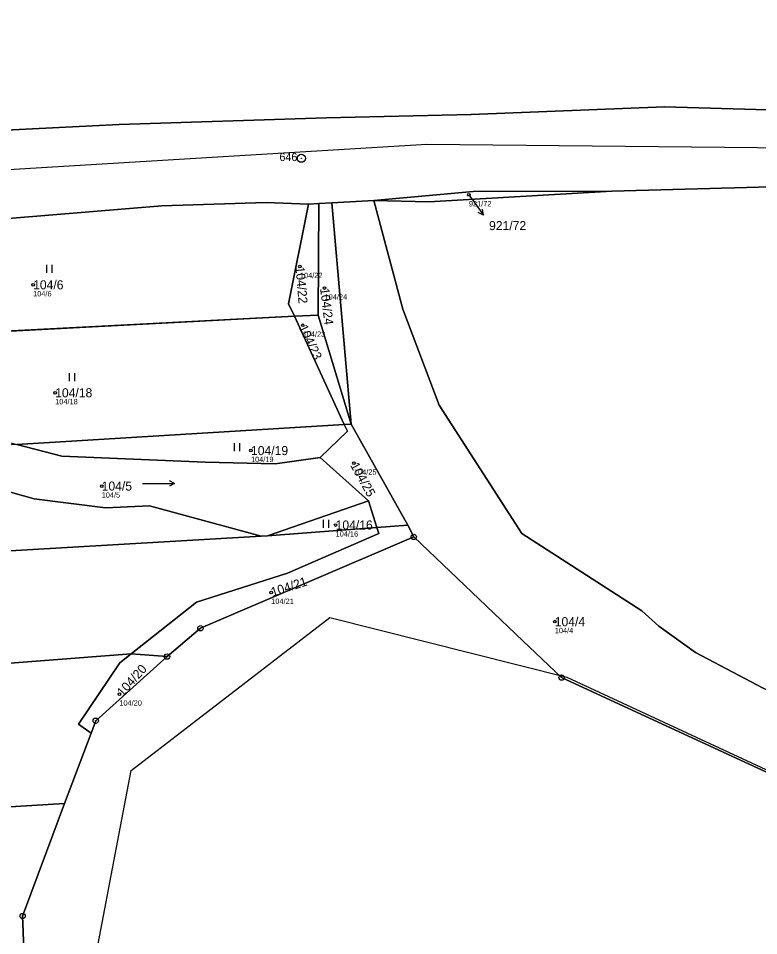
# Model space of a CAD drawing. Extents: x -734504 to -730695, y -1027923 to -1024502.
# Drawn here: x -731527.8 to -731389.2, y -1026155.5 to -1025983.6 of the extents above; entities that cross this region are included whole.
import ezdxf

# ---------------------------------------------------------------- set-up
doc = ezdxf.new("R2010")
doc.units = 0
for name, color, linetype in [('Definiční body', 7, 'Continuous'), ('Hranice parcel', 7, 'Continuous'), ('Parcelní čísla', 7, 'Continuous'), ('Polygon parcely', 7, 'Continuous'), ('Pop  PČ popisy', 7, 'Continuous'), ('Vnitřní kresba', 7, 'Continuous'), ('Značky bodu BP', 7, 'Continuous'), ('Značky kultur', 7, 'Continuous')]:
    doc.layers.add(name, color=color, linetype=linetype)

msp = doc.modelspace()

# ---------------------------------------------------------------- linework, layer by layer
at = {"layer": 'Definiční body'}
for centre in [(-731443.43, -1026016.73), (-731475.07, -1026030.16), (-731525.05, -1026033.58), (-731470.46, -1026034.18), (-731474.56, -1026041.16), (-731520.92, -1026053.81), (-731484.24, -1026064.64), (-731464.95, -1026067.01), (-731512.21, -1026071.29), (-731468.39, -1026078.59), (-731480.45, -1026091.22), (-731427.34, -1026096.7), (-731508.9, -1026110.27)]:
    msp.add_circle(centre, 0.25, dxfattribs=at)
at = {"layer": 'Hranice parcel'}
for p, q in [((-731477.2, -1026037.15), (-731473.47, -1026018.47)), ((-731473.47, -1026018.47), (-731471.55, -1026018.36)), ((-731471.68, -1026039.27), (-731471.55, -1026018.36)), ((-731471.55, -1026018.36), (-731469.07, -1026018.22)), ((-731461.25, -1026017.78), (-731469.07, -1026018.22)), ((-731469.07, -1026018.22), (-731465.5, -1026059.69)), ((-731476.12, -1026039.48), (-731477.2, -1026037.15)), ((-731568.83, -1026044.29), (-731476.12, -1026039.48)), ((-731476.12, -1026039.48), (-731471.68, -1026039.27)), ((-731466.76, -1026059.77), (-731476.12, -1026039.48)), ((-731465.5, -1026059.69), (-731471.68, -1026039.27)), ((-731528.11, -1026063.51), (-731466.76, -1026059.77)), ((-731466.76, -1026059.77), (-731465.5, -1026059.69)), ((-731466.19, -1026061.01), (-731466.76, -1026059.77)), ((-731465.5, -1026059.69), (-731454.89, -1026078.65)), ((-731471.3, -1026065.92), (-731466.19, -1026061.01)), ((-731462.23, -1026074.08), (-731471.3, -1026065.92)), ((-731481.14, -1026080.63), (-731462.23, -1026074.08)), ((-731460.65, -1026079.08), (-731462.23, -1026074.08)), ((-731460.65, -1026079.08), (-731481.14, -1026080.63)), ((-731454.89, -1026078.65), (-731460.65, -1026079.08)), ((-731454.89, -1026078.65), (-731453.76, -1026080.82)), ((-731580.71, -1026086.42), (-731482.31, -1026080.69)), ((-731482.31, -1026080.69), (-731481.14, -1026080.63)), ((-731506.7, -1026102.73), (-731588.4, -1026109.07)), ((-731499.97, -1026103.24), (-731506.7, -1026102.73)), ((-731514.2, -1026117.57), (-731519.15, -1026130.8)), ((-731519.15, -1026130.8), (-731596.66, -1026135.55))]:
    msp.add_line(p, q, dxfattribs=at)
for points in [[(-731897.94, -1025983.64), (-731862.07, -1025991.44), (-731847.22, -1025994.8), (-731827.82, -1025997.98), (-731799.13, -1026001.29), (-731775.22, -1026003.63), (-731763.84, -1026004.82), (-731742.5, -1026007.73), (-731730.75, -1026008.23), (-731698.59, -1026008.86), (-731662.59, -1026008.85), (-731619.31, -1026008.12), (-731589.11, -1026007.48), (-731575.19, -1026006.86), (-731508.93, -1026003.54), (-731470.15, -1026002.29), (-731442.98, -1026001.65), (-731406.79, -1026000.22), (-731383.28, -1026000.92)], [(-731311.13, -1026010.76), (-731350.25, -1026014.24), (-731416.63, -1026016)], [(-731416.63, -1026016), (-731450.95, -1026018.04), (-731461.25, -1026017.78)], [(-731461.25, -1026017.78), (-731449.48, -1026016.71), (-731442.63, -1026016.08), (-731416.63, -1026016)], [(-731473.47, -1026018.47), (-731481.39, -1026018.12), (-731500.93, -1026018.8), (-731528.93, -1026021.11), (-731573.67, -1026023.16)], [(-731461.25, -1026017.78), (-731455.79, -1026038.16), (-731448.97, -1026056.1), (-731433.52, -1026080.21), (-731411.05, -1026094.68), (-731407.88, -1026097.54), (-731400.99, -1026102.51), (-731376.79, -1026115.24), (-731363.17, -1026123.76), (-731346, -1026134.13), (-731334.78, -1026136.72)], [(-731471.3, -1026065.92), (-731479.74, -1026067.1), (-731492.82, -1026066.79), (-731519.69, -1026065.71), (-731528.11, -1026063.51)], [(-731555.24, -1026065.22), (-731541.77, -1026068.92), (-731524.83, -1026073.68), (-731511.48, -1026075.37), (-731503.25, -1026074.97), (-731482.31, -1026080.69)], [(-731506.7, -1026102.73), (-731494.43, -1026093.08), (-731477.42, -1026087.59), (-731460.31, -1026080.16), (-731460.65, -1026079.08)], [(-731453.76, -1026080.82), (-731493.71, -1026097.95), (-731499.97, -1026103.24)], [(-731453.76, -1026080.82), (-731433.31, -1026100.27), (-731426.05, -1026107.18), (-731411.21, -1026114.02), (-731343.39, -1026145.32)], [(-731514.2, -1026117.57), (-731516.54, -1026115.92), (-731508.81, -1026104.39), (-731506.7, -1026102.73)], [(-731499.97, -1026103.24), (-731513.33, -1026115.27), (-731514.2, -1026117.57)], [(-731519.15, -1026130.8), (-731522.52, -1026139.82), (-731527.02, -1026151.87), (-731526.93, -1026154.74), (-731526.81, -1026158.57)]]:
    msp.add_lwpolyline(points, dxfattribs=at)
at = {"layer": 'Polygon parcely'}
for points in [[(-731383.28, -1026000.92), (-731406.79, -1026000.22), (-731442.98, -1026001.65), (-731470.15, -1026002.29), (-731508.93, -1026003.54), (-731575.19, -1026006.86), (-731589.11, -1026007.48), (-731619.31, -1026008.12), (-731662.59, -1026008.85), (-731698.59, -1026008.86), (-731730.75, -1026008.23), (-731742.5, -1026007.73), (-731763.84, -1026004.82), (-731775.22, -1026003.63), (-731799.13, -1026001.29), (-731827.82, -1025997.98), (-731847.22, -1025994.8), (-731862.07, -1025991.44), (-731897.94, -1025983.64)], [(-731897.94, -1025983.64), (-731862.07, -1025991.44), (-731847.22, -1025994.8), (-731827.82, -1025997.98), (-731799.13, -1026001.29), (-731775.22, -1026003.63), (-731763.84, -1026004.82), (-731742.5, -1026007.73), (-731730.75, -1026008.23), (-731698.59, -1026008.86), (-731662.59, -1026008.85), (-731619.31, -1026008.12), (-731589.11, -1026007.48), (-731575.19, -1026006.86), (-731508.93, -1026003.54), (-731470.15, -1026002.29), (-731442.98, -1026001.65), (-731406.79, -1026000.22), (-731383.28, -1026000.92)], [(-731727.03, -1026023.83), (-731716.21, -1026023.81), (-731698.55, -1026023.77), (-731659.65, -1026023.51), (-731619.6, -1026023.97), (-731594.13, -1026022.85), (-731575.33, -1026023.13), (-731573.67, -1026023.16), (-731528.93, -1026021.11), (-731500.93, -1026018.8), (-731481.39, -1026018.12), (-731473.47, -1026018.47), (-731471.55, -1026018.36), (-731469.07, -1026018.22), (-731461.25, -1026017.78), (-731449.48, -1026016.71), (-731442.63, -1026016.08), (-731416.63, -1026016), (-731350.25, -1026014.24)], [(-731350.25, -1026014.24), (-731416.63, -1026016), (-731450.95, -1026018.04), (-731461.25, -1026017.78), (-731455.79, -1026038.16), (-731448.97, -1026056.1), (-731433.52, -1026080.21), (-731411.05, -1026094.68), (-731407.88, -1026097.54), (-731400.99, -1026102.51), (-731376.79, -1026115.24)], [(-731343.39, -1026145.32), (-731411.21, -1026114.02), (-731426.05, -1026107.18), (-731433.31, -1026100.27), (-731453.76, -1026080.82), (-731493.71, -1026097.95), (-731499.97, -1026103.24), (-731513.33, -1026115.27), (-731514.2, -1026117.57), (-731519.15, -1026130.8), (-731522.52, -1026139.82), (-731527.02, -1026151.87), (-731526.93, -1026154.74), (-731526.81, -1026158.57)]]:
    msp.add_lwpolyline(points, dxfattribs=at)
for points in [[(-731461.25, -1026017.78), (-731450.95, -1026018.04), (-731416.63, -1026016), (-731442.63, -1026016.08), (-731449.48, -1026016.71)], [(-731565.51, -1026035.89), (-731568.83, -1026044.29), (-731476.12, -1026039.48), (-731477.2, -1026037.15), (-731473.47, -1026018.47), (-731481.39, -1026018.12), (-731500.93, -1026018.8), (-731528.93, -1026021.11), (-731573.67, -1026023.16), (-731567.02, -1026030.49)], [(-731471.55, -1026018.36), (-731473.47, -1026018.47), (-731477.2, -1026037.15), (-731476.12, -1026039.48), (-731471.68, -1026039.27)], [(-731465.5, -1026059.69), (-731469.07, -1026018.22), (-731471.55, -1026018.36), (-731471.68, -1026039.27)], [(-731469.07, -1026018.22), (-731465.5, -1026059.69), (-731454.89, -1026078.65), (-731453.76, -1026080.82), (-731433.31, -1026100.27), (-731426.05, -1026107.18), (-731411.21, -1026114.02), (-731343.39, -1026145.32), (-731334.78, -1026136.72), (-731346, -1026134.13), (-731363.17, -1026123.76), (-731376.79, -1026115.24), (-731400.99, -1026102.51), (-731407.88, -1026097.54), (-731411.05, -1026094.68), (-731433.52, -1026080.21), (-731448.97, -1026056.1), (-731455.79, -1026038.16), (-731461.25, -1026017.78)], [(-731466.76, -1026059.77), (-731476.12, -1026039.48), (-731568.83, -1026044.29), (-731570.47, -1026048.43), (-731556.78, -1026054.6), (-731554.81, -1026056.52), (-731528.11, -1026063.51)], [(-731465.5, -1026059.69), (-731471.68, -1026039.27), (-731476.12, -1026039.48), (-731466.76, -1026059.77)], [(-731466.76, -1026059.77), (-731528.11, -1026063.51), (-731519.69, -1026065.71), (-731492.82, -1026066.79), (-731479.74, -1026067.1), (-731471.3, -1026065.92), (-731466.19, -1026061.01)], [(-731454.89, -1026078.65), (-731465.5, -1026059.69), (-731466.76, -1026059.77), (-731466.19, -1026061.01), (-731471.3, -1026065.92), (-731462.23, -1026074.08), (-731460.65, -1026079.08)], [(-731528.11, -1026063.51), (-731555.24, -1026065.22), (-731541.77, -1026068.92), (-731524.83, -1026073.68), (-731511.48, -1026075.37), (-731503.25, -1026074.97), (-731482.31, -1026080.69), (-731481.14, -1026080.63), (-731462.23, -1026074.08), (-731471.3, -1026065.92), (-731479.74, -1026067.1), (-731492.82, -1026066.79), (-731519.69, -1026065.71)], [(-731482.31, -1026080.69), (-731503.25, -1026074.97), (-731511.48, -1026075.37), (-731524.83, -1026073.68), (-731541.77, -1026068.92), (-731555.24, -1026065.22), (-731577.51, -1026066.62), (-731577.96, -1026072.72), (-731579.64, -1026083.26), (-731580.71, -1026086.42)], [(-731460.65, -1026079.08), (-731462.23, -1026074.08), (-731481.14, -1026080.63)], [(-731460.65, -1026079.08), (-731481.14, -1026080.63), (-731482.31, -1026080.69), (-731580.71, -1026086.42), (-731588.4, -1026109.07), (-731506.7, -1026102.73), (-731494.43, -1026093.08), (-731477.42, -1026087.59), (-731460.31, -1026080.16)], [(-731454.89, -1026078.65), (-731460.65, -1026079.08), (-731460.31, -1026080.16), (-731477.42, -1026087.59), (-731494.43, -1026093.08), (-731506.7, -1026102.73), (-731499.97, -1026103.24), (-731493.71, -1026097.95), (-731453.76, -1026080.82)], [(-731516.54, -1026115.92), (-731508.81, -1026104.39), (-731506.7, -1026102.73), (-731588.4, -1026109.07), (-731594.22, -1026126.22), (-731596.66, -1026135.55), (-731519.15, -1026130.8), (-731514.2, -1026117.57)], [(-731499.97, -1026103.24), (-731506.7, -1026102.73), (-731508.81, -1026104.39), (-731516.54, -1026115.92), (-731514.2, -1026117.57), (-731513.33, -1026115.27)], [(-731596.66, -1026135.55), (-731600.95, -1026151.92), (-731608.08, -1026163.26), (-731526.81, -1026158.57), (-731526.93, -1026154.74), (-731527.02, -1026151.87), (-731522.52, -1026139.82), (-731519.15, -1026130.8)]]:
    msp.add_lwpolyline(points, close=True, dxfattribs=at)
at = {"layer": 'Pop  PČ popisy'}
for p, q in [((-731443.43, -1026016.73), (-731442.43, -1026018.09)), ((-731442.43, -1026018.09), (-731440.67, -1026020.52)), ((-731440.67, -1026020.52), (-731441.66, -1026020)), ((-731440.67, -1026020.52), (-731440.85, -1026019.41))]:
    msp.add_line(p, q, dxfattribs=at)
at = {"layer": 'Vnitřní kresba'}
for points in [[(-731739.28, -1026015), (-731608.1, -1026016.73), (-731451.32, -1026007.24), (-731364.57, -1026008.08), (-731305.14, -1026012.49), (-731265.75, -1026016.16), (-731249.68, -1026018.55), (-731220.78, -1026024.33), (-731170.26, -1026039.02), (-731127.3, -1026055.65), (-731100.51, -1026067.24), (-731081.11, -1026075.58), (-731070.69, -1026082.31), (-731018.8, -1026119.92), (-730984.01, -1026148.82)], [(-731515.88, -1026172.81), (-731506.66, -1026124.59), (-731469.49, -1026095.91), (-731425.11, -1026107.08), (-731339.51, -1026146.85), (-731356.61, -1026182.38)]]:
    msp.add_lwpolyline(points, dxfattribs=at)
at = {"layer": 'Značky bodu BP'}
for centre, radius in [((-731474.81, -1026009.87), 0.75), ((-731474.81, -1026009.87), 0.03), ((-731453.76, -1026080.82), 0.5), ((-731453.76, -1026080.82), 0.0303), ((-731493.71, -1026097.95), 0.5), ((-731493.71, -1026097.95), 0.0303), ((-731499.97, -1026103.24), 0.5), ((-731499.97, -1026103.24), 0.0303), ((-731426.05, -1026107.18), 0.5), ((-731426.05, -1026107.18), 0.0303), ((-731513.33, -1026115.27), 0.5), ((-731513.33, -1026115.27), 0.0303), ((-731527.02, -1026151.87), 0.5), ((-731527.02, -1026151.87), 0.0303)]:
    msp.add_circle(centre, radius, dxfattribs=at)
at = {"layer": 'Značky kultur'}
for p, q in [((-731522.46, -1026031.31), (-731522.46, -1026029.81)), ((-731521.46, -1026031.31), (-731521.46, -1026029.81)), ((-731518.26, -1026051.61), (-731518.26, -1026050.11)), ((-731517.26, -1026051.61), (-731517.26, -1026050.11)), ((-731487.33, -1026064.78), (-731487.33, -1026063.28)), ((-731486.33, -1026064.78), (-731486.33, -1026063.28)), ((-731498.55, -1026070.83), (-731499.53, -1026070.33)), ((-731504.55, -1026070.83), (-731498.55, -1026070.83)), ((-731498.55, -1026070.83), (-731499.53, -1026071.33)), ((-731470.65, -1026079.15), (-731470.65, -1026077.65)), ((-731469.65, -1026079.15), (-731469.65, -1026077.65))]:
    msp.add_line(p, q, dxfattribs=at)

# ---------------------------------------------------------------- texts
at = {"layer": 'Definiční body'}
for s, p in [('921/72', (-731443.43, -1026018.89)), ('104/22', (-731475.07, -1026032.32)), ('104/6', (-731525.05, -1026035.74)), ('104/24', (-731470.46, -1026036.34)), ('104/23', (-731474.56, -1026043.32)), ('104/18', (-731520.92, -1026055.97)), ('104/19', (-731484.24, -1026066.8)), ('104/25', (-731464.95, -1026069.17)), ('104/5', (-731512.21, -1026073.45)), ('104/16', (-731468.39, -1026080.75)), ('104/21', (-731480.45, -1026093.38)), ('104/4', (-731427.34, -1026098.86)), ('104/20', (-731508.9, -1026112.43))]:
    msp.add_text(s, height=1, dxfattribs=at).set_placement(p)
at = {"layer": 'Parcelní čísla'}
for s, p in [('921/72', (-731439.65, -1026023.33)), ('104/6', (-731525.05, -1026034.43)), ('104/18', (-731520.92, -1026054.66)), ('104/19', (-731484.24, -1026065.49)), ('104/5', (-731512.21, -1026072.14)), ('104/16', (-731468.39, -1026079.44)), ('104/4', (-731427.34, -1026097.55))]:
    msp.add_text(s, height=1.7, dxfattribs=at).set_placement(p)
for s, rotation, p in [('104/22', 275, (-731475.92, -1026030.23)), ('104/24', 277, (-731471.3, -1026034.28)), ('104/23', 295, (-731475.33, -1026041.52)), ('104/25', 299, (-731465.69, -1026067.42)), ('104/21', 18, (-731480.19, -1026092.03)), ('104/20', 48, (-731508.27, -1026110.84))]:
    msp.add_text(s, height=1.7, rotation=rotation, dxfattribs=at).set_placement(p)
at = {"layer": 'Značky bodu BP'}
msp.add_text('646', height=1.5, dxfattribs=at).set_placement((-731478.91, -1026010.37))

doc.saveas('drawing.dxf')
